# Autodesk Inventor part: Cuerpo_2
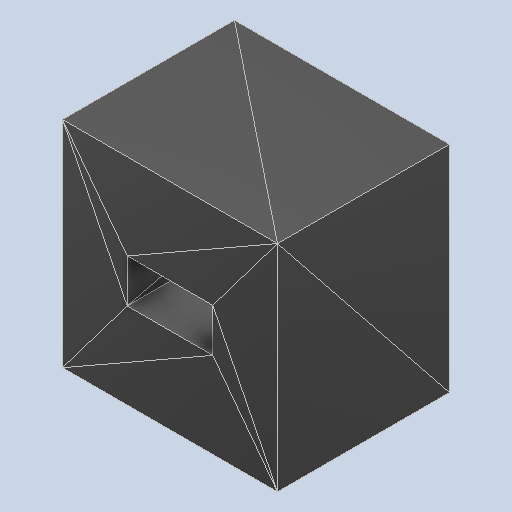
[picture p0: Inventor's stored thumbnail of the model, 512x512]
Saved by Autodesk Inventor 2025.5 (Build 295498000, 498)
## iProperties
Created: 2026-10
Part Number: Cuerpo_2
Material: Genérico
Document SubType Name: Modeling
Designer: Luis M
Density: 1 g/cm^3
Appearance: Valor por defecto
Author: Luis M
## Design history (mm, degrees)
feature "Base1"
node "Sólido1"
